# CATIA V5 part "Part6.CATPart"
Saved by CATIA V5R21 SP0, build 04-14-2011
Part number: Part6
Bounding box of the stored display mesh (mm): x 0 to 0, y -23 to 23, z -23 to 23
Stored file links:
  C:\Users\RIAD MAHAMUD PIASH\Desktop\Part6.CATPart
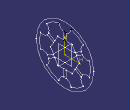
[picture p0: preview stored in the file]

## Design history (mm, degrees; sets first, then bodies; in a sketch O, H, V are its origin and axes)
Body1 (main body)
  Sketch1 on yz-plane, origin (0, 0, 0), H (0, 1, 0), V (0, 0, 1)
    circle A1 centre (0, 0) radius 23
    construction line L1 (0, 0) -> (28.2736, 16.3238)
    point P2 (11.5, 0)
    point P3 (5.75, 9.9593)
    point P4 (-5.75, 9.9593)
    point P5 (-11.5, 0)
    point P6 (-5.75, -9.9593)
    point P7 (5.75, -9.9593)
    point P8 (8.625, 4.9796)
    line L2 (11.5, 0) -> (9.125, 4.1136)
    line L3 (5.75, 9.9593) -> (1, 9.9593)
    line L4 (-5.75, 9.9593) -> (-8.125, 5.8457)
    line L5 (-11.5, 0) -> (-9.125, -4.1136)
    line L6 (-5.75, -9.9593) -> (-1, -9.9593)
    line L7 (5.75, -9.9593) -> (8.125, -5.8457)
    construction circle A2 centre (0, 0) radius 11.5
    construction arc A3 centre (-5.75, -9.9593) radius 11.5 from (-11.5, 0) to (5.75, -9.9593) cw
    construction arc A4 centre (5.75, 9.9593) radius 11.5 from (-5.75, 9.9593) to (11.5, 0) ccw
    arc A5 centre (0, 0) radius 20.5 from (14.7441, 14.2429) to (4.9627, 19.8902) ccw
    arc A6 centre (0, 20.5) radius 5 from (1, 15.601) to (4.9627, 19.8902) ccw
    line L8 (1, 15.601) -> (1, 9.9593)
    line L9 (-1, 15.601) -> (-1, 9.9593)
    point P12 (-1, 9.9593)
    arc A7 centre (0, 20.5) radius 5 from (-4.9627, 19.8902) to (-1, 15.601) ccw
    point P13 (-4.9627, 19.8902)
    line L10 (-13.0109, 8.6665) -> (-8.125, 5.8457)
    arc A8 centre (-17.7535, 10.25) radius 5 from (-13.0109, 8.6665) to (-14.7441, 14.2429) ccw
    line L11 (-14.0109, 6.9345) -> (-9.125, 4.1136)
    arc A9 centre (-17.7535, 10.25) radius 5 from (-19.7068, 5.6473) to (-14.0109, 6.9345) ccw
    line L12 (-14.0109, -6.9345) -> (-9.125, -4.1136)
    arc A10 centre (-17.7535, -10.25) radius 5 from (-14.0109, -6.9345) to (-19.7068, -5.6473) ccw
    line L13 (-13.0109, -8.6665) -> (-8.125, -5.8457)
    arc A11 centre (-17.7535, -10.25) radius 5 from (-14.7441, -14.2429) to (-13.0109, -8.6665) ccw
    line L14 (-1, -15.601) -> (-1, -9.9593)
    arc A12 centre (0, -20.5) radius 5 from (-1, -15.601) to (-4.9627, -19.8902) ccw
    line L15 (1, -15.601) -> (1, -9.9593)
    arc A13 centre (0, -20.5) radius 5 from (4.9627, -19.8902) to (1, -15.601) ccw
    line L16 (13.0109, -8.6665) -> (8.125, -5.8457)
    arc A14 centre (17.7535, -10.25) radius 5 from (13.0109, -8.6665) to (14.7441, -14.2429) ccw
    line L17 (14.0109, -6.9345) -> (9.125, -4.1136)
    arc A15 centre (17.7535, -10.25) radius 5 from (19.7068, -5.6473) to (14.0109, -6.9345) ccw
    line L18 (14.0109, 6.9345) -> (9.125, 4.1136)
    arc A16 centre (17.7535, 10.25) radius 5 from (14.0109, 6.9345) to (19.7068, 5.6473) ccw
    line L19 (13.0109, 8.6665) -> (8.125, 5.8457)
    arc A17 centre (17.7535, 10.25) radius 5 from (14.7441, 14.2429) to (13.0109, 8.6665) ccw
    line L20 (1, 15.601) -> (1, 9.9593)
    arc A18 centre (0, 20.5) radius 5 from (1, 15.601) to (4.9627, 19.8902) ccw
    line L21 (-1, 15.601) -> (-1, 9.9593)
    arc A19 centre (0, 20.5) radius 5 from (-4.9627, 19.8902) to (-1, 15.601) ccw
    line L22 (-1, 9.9593) -> (-5.75, 9.9593)
    line L23 (-9.125, 4.1136) -> (-11.5, 0)
    line L24 (-8.125, -5.8457) -> (-5.75, -9.9593)
    line L25 (1, -9.9593) -> (5.75, -9.9593)
    line L26 (9.125, -4.1136) -> (11.5, 0)
    line L27 (8.125, 5.8457) -> (5.75, 9.9593)
    arc A20 centre (0, 0) radius 20.5 from (-4.9627, 19.8902) to (-14.7441, 14.2429) ccw
    arc A21 centre (0, 0) radius 20.5 from (-19.7068, 5.6473) to (-19.7068, -5.6473) ccw
    arc A22 centre (0, 0) radius 20.5 from (-14.7441, -14.2429) to (-4.9627, -19.8902) ccw
    arc A23 centre (0, 0) radius 20.5 from (4.9627, -19.8902) to (14.7441, -14.2429) ccw
    arc A24 centre (0, 0) radius 20.5 from (19.7068, -5.6473) to (19.7068, 5.6473) ccw
    radius A1 = 23
    angle L1 H = 30
    distance P3 O = 11.5
    radius A5 = 20.5
    radius A6 = 5
    coincidence: A2 P2, A2 P3, A2 P4, A2 P5, A2 P6, A2 P7, L3 P12, A5 P13, A6 A7, L3 L22, L4 L23, L5 L24, L6 L25, L7 L26, L2 P8, L2 L27, A5 A20, A20 A21, A21 A22, A22 A23, A23 A24
    parallelism: L2 L5
    vertical: L9 V
    equidistance: P2 P3 P8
